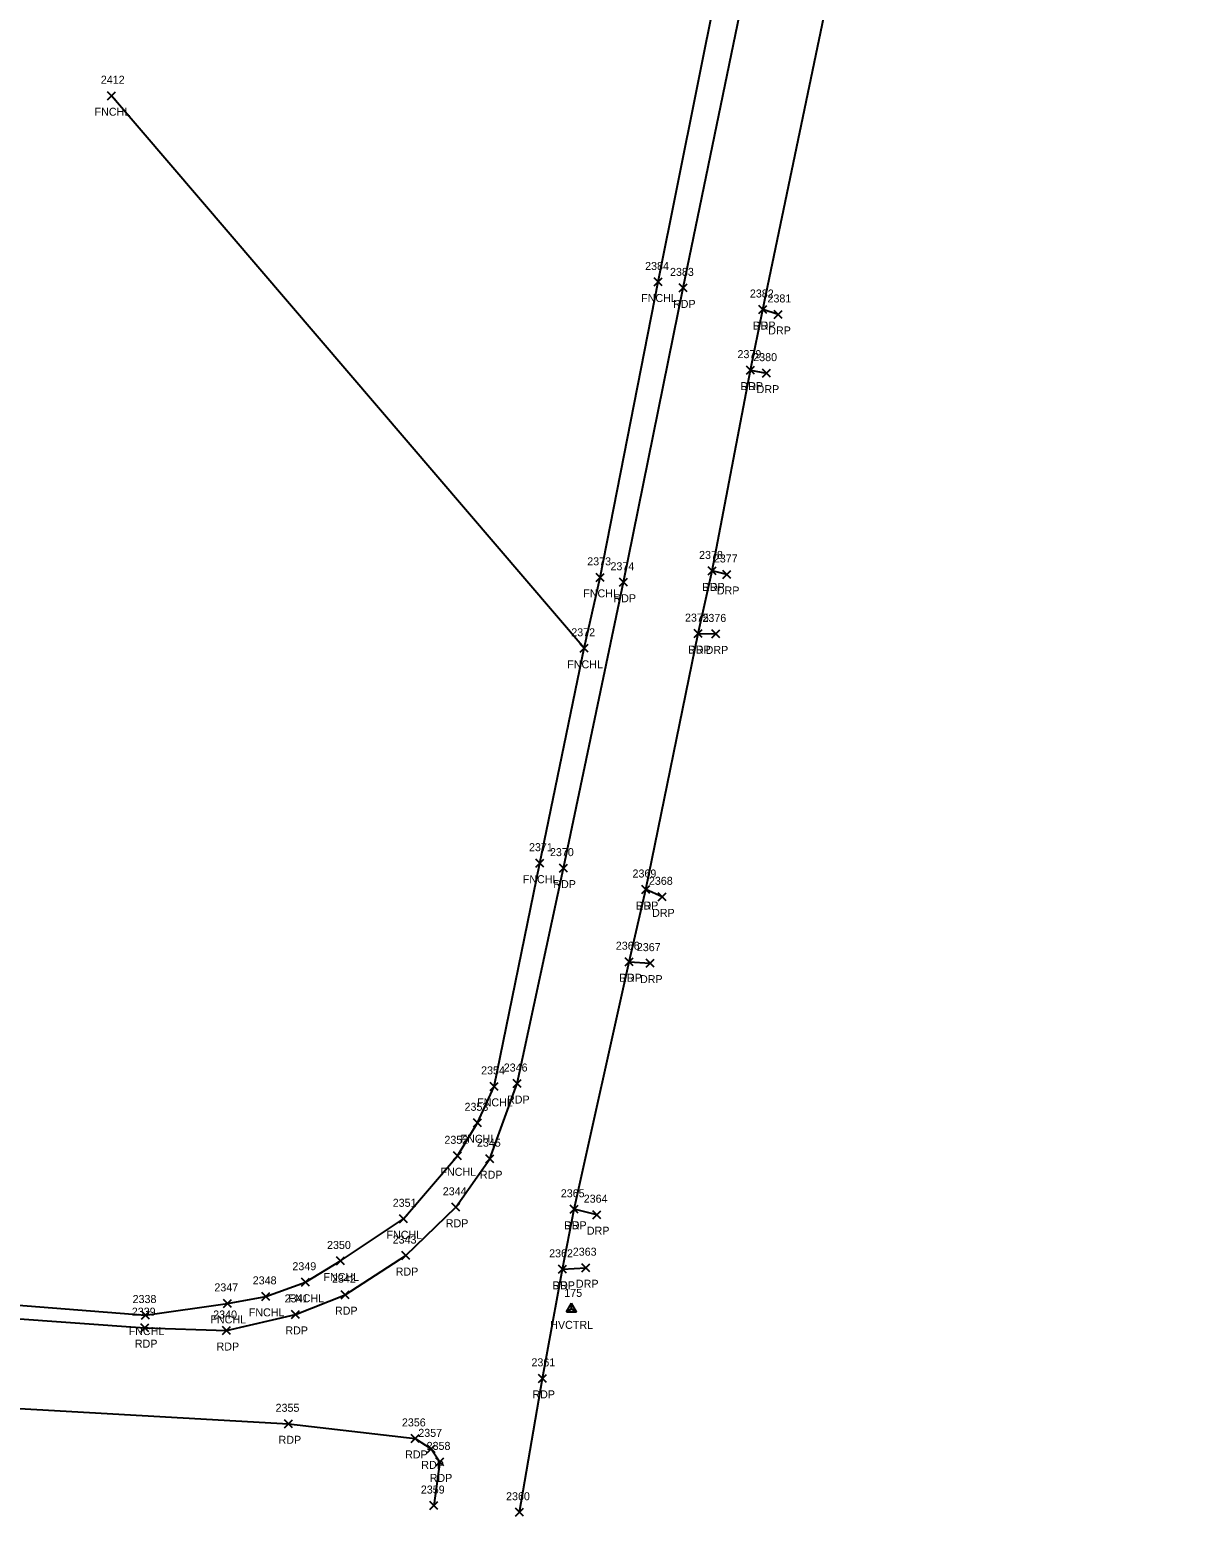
# Model space of a CAD drawing. Extents: x 1767353 to 1772625, y 740790 to 747702.
# Drawn here: x 1770915.9 to 1771206.2, y 742358.8 to 742730.2 of the extents above; entities that cross this region are included whole.
import ezdxf

# ---------------------------------------------------------------- set-up
doc = ezdxf.new("R2010")
doc.units = 0
for name, color, linetype in [('C_A', 7, 'Continuous'), ('C_I', 7, 'Continuous'), ('CPSM', 7, 'Continuous'), ('L_A', 7, 'Continuous'), ('L_I', 7, 'Continuous'), ('L_TIC', 7, 'Continuous'), ('LFNC', 7, 'Continuous'), ('P_A', 7, 'Continuous'), ('P_I', 7, 'Continuous'), ('P_TIC', 7, 'Continuous'), ('PET', 7, 'Continuous'), ('R_A', 7, 'Continuous'), ('R_I', 7, 'Continuous'), ('R_TIC', 7, 'Continuous'), ('RDP', 7, 'Continuous')]:
    doc.layers.add(name, color=color, linetype=linetype)

msp = doc.modelspace()

# ---------------------------------------------------------------- linework, layer by layer
at = {"layer": 'CPSM'}
for p, q in [((1771050.04, 742409.86), (1771051.29, 742412.02)), ((1771050.04, 742409.86), (1771051.29, 742412.02)), ((1771050.04, 742409.86), (1771051.29, 742412.02)), ((1771050.04, 742409.86), (1771051.29, 742412.02)), ((1771050.04, 742409.86), (1771051.29, 742410.58)), ((1771050.04, 742409.86), (1771051.29, 742410.58)), ((1771050.04, 742409.86), (1771051.29, 742410.58)), ((1771050.04, 742409.86), (1771051.29, 742410.58)), ((1771050.04, 742409.86), (1771052.54, 742409.86)), ((1771050.04, 742409.86), (1771052.54, 742409.86)), ((1771050.04, 742409.86), (1771052.54, 742409.86)), ((1771050.04, 742409.86), (1771052.54, 742409.86)), ((1771052.54, 742409.86), (1771051.29, 742412.02)), ((1771051.29, 742410.58), (1771051.29, 742412.02)), ((1771052.54, 742409.86), (1771051.29, 742412.02)), ((1771051.29, 742410.58), (1771051.29, 742412.02)), ((1771052.54, 742409.86), (1771051.29, 742412.02)), ((1771051.29, 742410.58), (1771051.29, 742412.02)), ((1771052.54, 742409.86), (1771051.29, 742412.02)), ((1771051.29, 742410.58), (1771051.29, 742412.02)), ((1771051.29, 742410.58), (1771051.29, 742410.58)), ((1771051.29, 742410.58), (1771052.54, 742409.86)), ((1771051.29, 742410.58), (1771051.29, 742410.58)), ((1771051.29, 742410.58), (1771052.54, 742409.86)), ((1771051.29, 742410.58), (1771051.29, 742410.58)), ((1771051.29, 742410.58), (1771052.54, 742409.86)), ((1771051.29, 742410.58), (1771051.29, 742410.58)), ((1771051.29, 742410.58), (1771052.54, 742409.86))]:
    msp.add_line(p, q, dxfattribs=at)
at = {"layer": 'L_TIC'}
for points in [[(1770935.36, 742712.7), (1770937.36, 742714.7)], [(1770937.36, 742712.7), (1770935.36, 742714.7)], [(1771071.95, 742666.16), (1771073.95, 742668.16)], [(1771073.95, 742666.16), (1771071.95, 742668.16)], [(1771057.48, 742592.36), (1771059.48, 742594.36)], [(1771059.48, 742592.36), (1771057.48, 742594.36)], [(1771053.49, 742574.63), (1771055.49, 742576.63)], [(1771055.49, 742574.63), (1771053.49, 742576.63)], [(1771053.49, 742574.63), (1771055.49, 742576.63)], [(1771055.49, 742574.63), (1771053.49, 742576.63)], [(1771042.36, 742520.94), (1771044.36, 742522.94)], [(1771044.36, 742520.94), (1771042.36, 742522.94)], [(1771030.96, 742465.17), (1771032.96, 742467.17)], [(1771032.96, 742465.17), (1771030.96, 742467.17)], [(1771026.82, 742456.07), (1771028.82, 742458.07)], [(1771028.82, 742456.07), (1771026.82, 742458.07)], [(1771021.79, 742447.82), (1771023.79, 742449.82)], [(1771023.79, 742447.82), (1771021.79, 742449.82)], [(1771008.31, 742432.08), (1771010.31, 742434.08)], [(1771010.31, 742432.08), (1771008.31, 742434.08)], [(1770992.55, 742421.55), (1770994.55, 742423.55)], [(1770994.55, 742421.55), (1770992.55, 742423.55)], [(1770983.8, 742416.23), (1770985.8, 742418.23)], [(1770985.8, 742416.23), (1770983.8, 742418.23)], [(1770964.3, 742410.95), (1770966.3, 742412.95)], [(1770966.3, 742410.95), (1770964.3, 742412.95)], [(1770973.89, 742412.7), (1770975.89, 742414.7)], [(1770975.89, 742412.7), (1770973.89, 742414.7)], [(1770943.87, 742408.03), (1770945.87, 742410.03)], [(1770945.87, 742408.03), (1770943.87, 742410.03)]]:
    msp.add_lwpolyline(points, dxfattribs=at)
at = {"layer": 'LFNC'}
for points in [[(1770709.62, 742441.85), (1770732.27, 742435), (1770776.72, 742423.71), (1770858.12, 742415.82), (1770944.87, 742409.03), (1770965.3, 742411.95), (1770974.89, 742413.7), (1770984.8, 742417.23), (1770993.55, 742422.55), (1771009.31, 742433.08), (1771022.79, 742448.82), (1771027.82, 742457.07), (1771031.96, 742466.17), (1771043.36, 742521.94), (1771054.49, 742575.63), (1771058.48, 742593.36), (1771072.95, 742667.16), (1771097.46, 742789.3), (1771131.95, 742961.2), (1771147.21, 743037.58), (1771136.95, 743059.9)], [(1771054.49, 742575.63), (1770936.36, 742713.7)]]:
    msp.add_lwpolyline(points, dxfattribs=at)
at = {"layer": 'P_TIC'}
for points in [[(1771078.17, 742664.68), (1771080.17, 742666.68)], [(1771080.17, 742664.68), (1771078.17, 742666.68)], [(1771098.13, 742659.28), (1771100.13, 742661.28)], [(1771100.13, 742659.28), (1771098.13, 742661.28)], [(1771095.03, 742644.13), (1771097.03, 742646.13)], [(1771097.03, 742644.13), (1771095.03, 742646.13)], [(1771085.43, 742593.96), (1771087.43, 742595.96)], [(1771087.43, 742593.96), (1771085.43, 742595.96)], [(1771063.29, 742591.13), (1771065.29, 742593.13)], [(1771065.29, 742591.13), (1771063.29, 742593.13)], [(1771081.91, 742578.3), (1771083.91, 742580.3)], [(1771083.91, 742578.3), (1771081.91, 742580.3)], [(1771048.26, 742519.7), (1771050.26, 742521.7)], [(1771050.26, 742519.7), (1771048.26, 742521.7)], [(1771068.85, 742514.36), (1771070.85, 742516.36)], [(1771070.85, 742514.36), (1771068.85, 742516.36)], [(1771064.72, 742496.32), (1771066.72, 742498.32)], [(1771066.72, 742496.32), (1771064.72, 742498.32)], [(1771036.68, 742465.88), (1771038.68, 742467.88)], [(1771038.68, 742465.88), (1771036.68, 742467.88)], [(1771029.92, 742447.1), (1771031.92, 742449.1)], [(1771031.92, 742447.1), (1771029.92, 742449.1)], [(1771021.38, 742434.96), (1771023.38, 742436.96)], [(1771023.38, 742434.96), (1771021.38, 742436.96)], [(1771050.93, 742434.46), (1771052.93, 742436.46)], [(1771052.93, 742434.46), (1771050.93, 742436.46)], [(1771008.86, 742422.89), (1771010.86, 742424.89)], [(1771010.86, 742422.89), (1771008.86, 742424.89)], [(1771048.01, 742419.46), (1771050.01, 742421.46)], [(1771050.01, 742419.46), (1771048.01, 742421.46)], [(1770993.69, 742413.12), (1770995.69, 742415.12)], [(1770995.69, 742413.12), (1770993.69, 742415.12)], [(1770981.29, 742408.19), (1770983.29, 742410.19)], [(1770983.29, 742408.19), (1770981.29, 742410.19)], [(1770943.68, 742404.88), (1770945.68, 742406.88)], [(1770945.68, 742404.88), (1770943.68, 742406.88)], [(1770964.1, 742404.17), (1770966.1, 742406.17)], [(1770966.1, 742404.17), (1770964.1, 742406.17)], [(1771043.02, 742392.22), (1771045.02, 742394.22)], [(1771045.02, 742392.22), (1771043.02, 742394.22)], [(1770979.6, 742380.86), (1770981.6, 742382.86)], [(1770981.6, 742380.86), (1770979.6, 742382.86)], [(1771011.22, 742377.21), (1771013.22, 742379.21)], [(1771013.22, 742377.21), (1771011.22, 742379.21)], [(1771015.26, 742374.6), (1771017.26, 742376.6)], [(1771017.26, 742374.6), (1771015.26, 742376.6)], [(1771017.35, 742371.34), (1771019.35, 742373.34)], [(1771019.35, 742371.34), (1771017.35, 742373.34)], [(1771015.91, 742360.43), (1771017.91, 742362.43)], [(1771017.91, 742360.43), (1771015.91, 742362.43)], [(1771037.33, 742358.76), (1771039.33, 742360.76)], [(1771039.33, 742358.76), (1771037.33, 742360.76)]]:
    msp.add_lwpolyline(points, dxfattribs=at)
at = {"layer": 'PET'}
for points in [[(1771038.33, 742359.76), (1771044.02, 742393.22), (1771049.01, 742420.46), (1771051.93, 742435.46), (1771065.72, 742497.32), (1771069.85, 742515.36), (1771082.91, 742579.3), (1771086.43, 742594.96), (1771096.03, 742645.13), (1771099.13, 742660.28), (1771115.59, 742739.41), (1771120, 742760.61), (1771124.82, 742784.85), (1771132.32, 742822.33), (1771135.64, 742843), (1771145.63, 742889.63), (1771149.81, 742909.39), (1771156.21, 742941.67), (1771158.59, 742954.59), (1771172.11, 743020.68), (1771206.18, 743013.84)], [(1770560.4, 742444.06), (1770632.97, 742437.3), (1770743.12, 742423.11), (1770776.64, 742419.53), (1770857.56, 742412.05), (1770944.68, 742405.88), (1770965.1, 742405.17), (1770982.29, 742409.19), (1770994.69, 742414.12), (1771009.86, 742423.89), (1771022.38, 742435.96), (1771030.92, 742448.1), (1771037.68, 742466.88), (1771049.26, 742520.7), (1771064.29, 742592.13), (1771079.17, 742665.68), (1771104.37, 742787.53)], [(1770558.07, 742420.21), (1770594.59, 742416.67), (1770610.1, 742414.61), (1770644.11, 742413.83), (1770677.13, 742407.98), (1770724.81, 742402.17), (1770739.48, 742400.39), (1770769.32, 742397.75), (1770789.15, 742394.42), (1770803.42, 742393.52), (1770841.15, 742389.93), (1770854.69, 742389.02), (1770980.6, 742381.86), (1771012.22, 742378.21), (1771016.26, 742375.6), (1771018.35, 742372.34), (1771016.91, 742361.43)]]:
    msp.add_lwpolyline(points, dxfattribs=at)
at = {"layer": 'R_TIC'}
for points in [[(1771098.13, 742659.28), (1771100.13, 742661.28)], [(1771100.13, 742659.28), (1771098.13, 742661.28)], [(1771101.97, 742658.05), (1771103.97, 742660.05)], [(1771103.97, 742658.05), (1771101.97, 742660.05)], [(1771095.03, 742644.13), (1771097.03, 742646.13)], [(1771097.03, 742644.13), (1771095.03, 742646.13)], [(1771099.06, 742643.38), (1771101.06, 742645.38)], [(1771101.06, 742643.38), (1771099.06, 742645.38)], [(1771085.43, 742593.96), (1771087.43, 742595.96)], [(1771087.43, 742593.96), (1771085.43, 742595.96)], [(1771089.12, 742593.08), (1771091.12, 742595.08)], [(1771091.12, 742593.08), (1771089.12, 742595.08)], [(1771081.91, 742578.3), (1771083.91, 742580.3)], [(1771083.91, 742578.3), (1771081.91, 742580.3)], [(1771086.32, 742578.22), (1771088.32, 742580.22)], [(1771088.32, 742578.22), (1771086.32, 742580.22)], [(1771068.85, 742514.36), (1771070.85, 742516.36)], [(1771070.85, 742514.36), (1771068.85, 742516.36)], [(1771072.94, 742512.53), (1771074.94, 742514.53)], [(1771074.94, 742512.53), (1771072.94, 742514.53)], [(1771064.72, 742496.32), (1771066.72, 742498.32)], [(1771066.72, 742496.32), (1771064.72, 742498.32)], [(1771069.93, 742495.96), (1771071.93, 742497.96)], [(1771071.93, 742495.96), (1771069.93, 742497.96)], [(1771050.93, 742434.46), (1771052.93, 742436.46)], [(1771052.93, 742434.46), (1771050.93, 742436.46)], [(1771056.65, 742433.11), (1771058.65, 742435.11)], [(1771058.65, 742433.11), (1771056.65, 742435.11)], [(1771048.01, 742419.46), (1771050.01, 742421.46)], [(1771050.01, 742419.46), (1771048.01, 742421.46)], [(1771053.91, 742419.86), (1771055.91, 742421.86)], [(1771055.91, 742419.86), (1771053.91, 742421.86)]]:
    msp.add_lwpolyline(points, dxfattribs=at)
at = {"layer": 'RDP'}
for points in [[(1771102.97, 742659.05), (1771099.13, 742660.28)], [(1771096.03, 742645.13), (1771100.06, 742644.38)], [(1771090.12, 742594.08), (1771086.43, 742594.96)], [(1771082.91, 742579.3), (1771087.32, 742579.22)], [(1771073.94, 742513.53), (1771069.85, 742515.36)], [(1771065.72, 742497.32), (1771070.93, 742496.96)], [(1771057.65, 742434.11), (1771051.93, 742435.46)], [(1771049.01, 742420.46), (1771054.91, 742420.86)]]:
    msp.add_lwpolyline(points, dxfattribs=at)

# ---------------------------------------------------------------- texts
at = {"layer": 'C_A'}
msp.add_text('HVCTRL', height=2, dxfattribs=at).set_placement((1771045.98, 742405.58))
msp.add_text('HVCTRL', height=2, dxfattribs=at).set_placement((1771045.98, 742405.58))
msp.add_text('HVCTRL', height=2, dxfattribs=at).set_placement((1771045.98, 742405.58))
msp.add_text('HVCTRL', height=2, dxfattribs=at).set_placement((1771045.98, 742405.58))
at = {"layer": 'C_I'}
msp.add_text('175', height=2, dxfattribs=at).set_placement((1771049.49, 742413.58))
msp.add_text('175', height=2, dxfattribs=at).set_placement((1771049.49, 742413.58))
msp.add_text('175', height=2, dxfattribs=at).set_placement((1771049.49, 742413.58))
msp.add_text('175', height=2, dxfattribs=at).set_placement((1771049.49, 742413.58))
at = {"layer": 'L_A'}
for p in [(1770932.11, 742708.7), (1771068.7, 742662.16), (1771054.23, 742588.36), (1771050.23, 742570.63), (1771050.23, 742570.63), (1771039.11, 742516.94), (1771027.71, 742461.17), (1771023.57, 742452.07), (1771018.54, 742443.82), (1771005.05, 742428.08), (1770989.3, 742417.55), (1770980.55, 742412.23), (1770961.04, 742406.95), (1770970.64, 742408.7), (1770940.62, 742404.03)]:
    msp.add_text('FNCHL', height=2, dxfattribs=at).set_placement(p)
at = {"layer": 'L_I'}
for s, p in [('2412', (1770933.67, 742716.7)), ('2384', (1771069.69, 742670.16)), ('2373', (1771055.22, 742596.36)), ('2372', (1771051.23, 742578.63)), ('2372', (1771051.23, 742578.63)), ('2371', (1771040.67, 742524.94)), ('2354', (1771028.7, 742469.17)), ('2353', (1771024.56, 742460.07)), ('2352', (1771019.53, 742451.82)), ('2351', (1771006.61, 742436.08)), ('2350', (1770990.2, 742425.55)), ('2349', (1770981.54, 742420.23)), ('2347', (1770962.04, 742414.95)), ('2348', (1770971.63, 742416.7)), ('2338', (1770941.61, 742412.03))]:
    msp.add_text(s, height=2, dxfattribs=at).set_placement(p)
at = {"layer": 'P_A'}
for p in [(1771076.65, 742660.68), (1771096.62, 742655.28), (1771093.52, 742640.13), (1771083.91, 742589.96), (1771061.78, 742587.13), (1771080.4, 742574.3), (1771046.74, 742515.7), (1771067.34, 742510.36), (1771063.21, 742492.32), (1771035.17, 742461.88), (1771028.4, 742443.1), (1771019.87, 742430.96), (1771049.42, 742430.46), (1771007.35, 742418.89), (1771046.5, 742415.46), (1770992.18, 742409.12), (1770979.78, 742404.19), (1770942.17, 742400.88), (1770962.59, 742400.17), (1771041.51, 742388.22), (1770978.09, 742376.86), (1771009.71, 742373.21), (1771013.75, 742370.6), (1771015.84, 742367.34)]:
    msp.add_text('RDP', height=2, dxfattribs=at).set_placement(p)
at = {"layer": 'P_I'}
for s, p in [('2383', (1771075.91, 742668.68)), ('2382', (1771095.87, 742663.28)), ('2379', (1771092.77, 742648.13)), ('2378', (1771083.17, 742597.96)), ('2374', (1771061.03, 742595.13)), ('2375', (1771079.65, 742582.3)), ('2370', (1771045.91, 742523.7)), ('2369', (1771066.54, 742518.36)), ('2366', (1771062.36, 742500.32)), ('2346', (1771034.36, 742469.88)), ('2345', (1771027.66, 742451.1)), ('2344', (1771019.12, 742438.96)), ('2365', (1771048.62, 742438.46)), ('2343', (1771006.6, 742426.89)), ('2362', (1771045.7, 742423.46)), ('2342', (1770991.43, 742417.12)), ('2341', (1770979.6, 742412.19)), ('2339', (1770941.41, 742408.88)), ('2340', (1770961.75, 742408.17)), ('2361', (1771041.28, 742396.22)), ('2355', (1770977.34, 742384.86)), ('2356', (1771008.91, 742381.21)), ('2357', (1771013, 742378.6)), ('2358', (1771015.09, 742375.34)), ('2359', (1771013.64, 742364.43)), ('2360', (1771034.94, 742362.76))]:
    msp.add_text(s, height=2, dxfattribs=at).set_placement(p)
at = {"layer": 'R_A'}
for p in [(1771096.62, 742655.28), (1771100.46, 742654.05), (1771093.52, 742640.13), (1771097.55, 742639.38), (1771083.91, 742589.96), (1771087.61, 742589.08), (1771080.4, 742574.3), (1771084.81, 742574.22), (1771067.34, 742510.36), (1771071.43, 742508.53), (1771063.21, 742492.32), (1771068.41, 742491.96), (1771049.42, 742430.46), (1771055.13, 742429.11), (1771046.5, 742415.46), (1771052.4, 742415.86)]:
    msp.add_text('DRP', height=2, dxfattribs=at).set_placement(p)
at = {"layer": 'R_I'}
for s, p in [('2382', (1771095.87, 742663.28)), ('2381', (1771100.27, 742662.05)), ('2379', (1771092.77, 742648.13)), ('2380', (1771096.71, 742647.38)), ('2378', (1771083.17, 742597.96)), ('2377', (1771086.86, 742597.08)), ('2375', (1771079.65, 742582.3)), ('2376', (1771084.01, 742582.22)), ('2369', (1771066.54, 742518.36)), ('2368', (1771070.64, 742516.53)), ('2366', (1771062.36, 742500.32)), ('2367', (1771067.62, 742499.96)), ('2365', (1771048.62, 742438.46)), ('2364', (1771054.34, 742437.11)), ('2362', (1771045.7, 742423.46)), ('2363', (1771051.61, 742423.86))]:
    msp.add_text(s, height=2, dxfattribs=at).set_placement(p)

doc.saveas('drawing.dxf')
